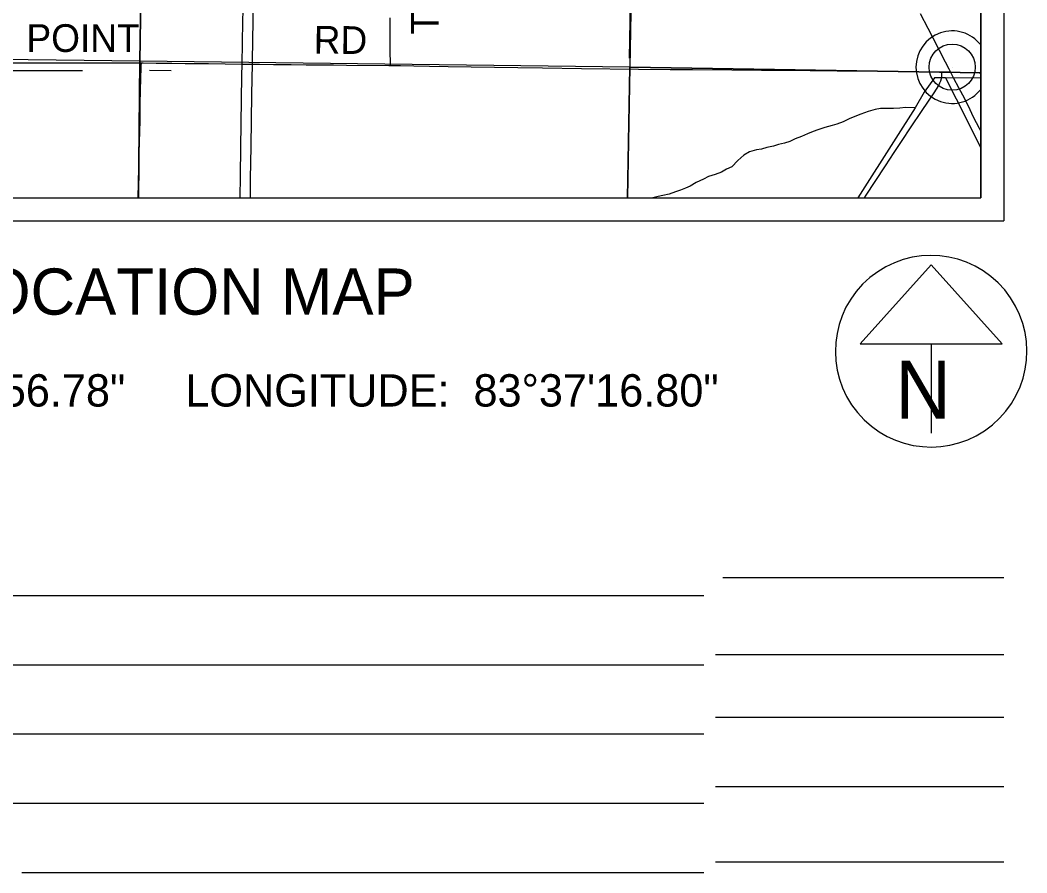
# Model space of a CAD drawing. Extents: x -5.6 to 34, y 0 to 22.
# Drawn here: x 4.739 to 9.099, y 11.177 to 14.869 of the extents above; entities that cross this region are included whole.
import ezdxf

# ---------------------------------------------------------------- set-up
doc = ezdxf.new("R2010")
doc.units = 0
for name, color, linetype in [('GM_X_Interstate_Route', 7, 'Continuous'), ('GM_X_Minor_River', 7, 'Continuous'), ('GM_X_Section', 7, 'Continuous'), ('GM_X_State_Route', 7, 'Continuous'), ('GM_X_Township', 7, 'Continuous'), ('GM_X_Township_Road', 7, 'Continuous'), ('GM_X_Township_Road_Text', 7, 'Continuous'), ('GM_X_Unincorporated', 7, 'Continuous'), ('GM_X_Unincorporated_Location', 7, 'Continuous'), ('SH_Data', 7, 'Continuous'), ('SH_Text', 7, 'Continuous')]:
    doc.layers.add(name, color=color, linetype=linetype)

msp = doc.modelspace()

# ---------------------------------------------------------------- linework, layer by layer
at = {"layer": 'GM_X_Interstate_Route'}
for points in [[(5.7358, 14.1), (5.7369, 14.1817), (5.7387, 14.3222), (5.7425, 14.5493), (5.7447, 14.6786), (5.745, 14.6938), (5.7503, 15.0391)], [(5.6912, 14.1), (5.6926, 14.1951), (5.6944, 14.3172), (5.6993, 14.6284), (5.7002, 14.6792), (5.7034, 14.8634), (5.704, 14.912)]]:
    msp.add_lwpolyline(points, dxfattribs=at)
at = {"layer": 'GM_X_Minor_River'}
for points in [[(7.3779, 14.7044), (7.3837, 15.0298), (7.3962, 15.4993), (7.4047, 15.9625), (7.4129, 16.2894), (7.4222, 16.7566)], [(3.6761, 14.6605), (3.815, 14.6604), (3.9826, 14.6579), (4.2141, 14.6562), (4.4447, 14.6522), (4.701, 14.6508), (5.0092, 14.6513)], [(5.299, 14.6523), (5.3932, 14.6508)], [(8.9, 14.6183), (8.7475, 14.6191), (8.6988, 14.6197), (8.6541, 14.5578), (8.615, 14.4901), (8.5311, 14.3581), (8.3669, 14.1)], [(8.7475, 14.6191), (8.8393, 14.4376), (8.9, 14.3153)], [(8.615, 14.4901), (8.5743, 14.4907), (8.5495, 14.4878), (8.5216, 14.4865), (8.4928, 14.4869), (8.4657, 14.4864), (8.4417, 14.4827), (8.4121, 14.4735), (8.38, 14.4626), (8.3544, 14.4517), (8.3303, 14.4416), (8.303, 14.4283), (8.2765, 14.419), (8.2565, 14.4129), (8.2237, 14.4045), (8.1933, 14.3944), (8.1732, 14.3875), (8.1491, 14.3766), (8.1227, 14.3657), (8.0954, 14.3548), (8.0729, 14.3438), (8.0497, 14.3369), (8.0241, 14.3308), (8.0024, 14.3239), (7.9736, 14.3178), (7.9496, 14.3109), (7.928, 14.3072), (7.8976, 14.2995), (7.8727, 14.2838), (7.8477, 14.2617), (7.8218, 14.234), (7.7985, 14.2238), (7.776, 14.2113), (7.7495, 14.2012), (7.7199, 14.192), (7.6982, 14.181), (7.6669, 14.1662), (7.6412, 14.1505), (7.6211, 14.1411), (7.5995, 14.1334), (7.577, 14.1264), (7.5506, 14.1163), (7.5226, 14.1103), (7.5018, 14.1049), (7.479, 14.1)]]:
    msp.add_lwpolyline(points, dxfattribs=at)
at = {"layer": 'GM_X_Section'}
for points in [[(3.1401, 16.8587), (5.2895, 16.8144), (5.2575, 14.6921), (3.0791, 14.7168)], [(5.2895, 16.8144), (7.4183, 16.7871), (7.3798, 14.6657), (5.2575, 14.6921)], [(8.9, 14.6404), (8.9, 16.7658), (7.4183, 16.7871), (7.3798, 14.6657)], [(3.0658, 14.1), (5.2509, 14.1), (5.2575, 14.6921), (3.0791, 14.7168)], [(5.2509, 14.1), (7.3694, 14.1), (7.3798, 14.6657), (5.2575, 14.6921)], [(7.3694, 14.1), (8.9, 14.1), (8.9, 14.6404), (7.3798, 14.6657)]]:
    msp.add_lwpolyline(points, close=True, dxfattribs=at)
at = {"layer": 'GM_X_State_Route'}
msp.add_lwpolyline([(8.9, 14.3878), (8.8937, 14.4001), (8.8685, 14.4496), (8.8531, 14.4812), (8.8331, 14.5221), (8.8225, 14.5437), (8.805, 14.576), (8.7836, 14.6167), (8.7688, 14.6447), (8.7622, 14.6573), (8.7464, 14.6876), (8.7205, 14.7377), (8.693, 14.7915), (8.6718, 14.8323), (8.6388, 14.8965)], dxfattribs=at)
at = {"layer": 'GM_X_Township'}
msp.add_lwpolyline([(3.0636, 14.1), (8.9, 14.1), (8.9, 20.9), (2.1, 20.9), (2.1, 16.9108), (2.7242, 16.8707), (3.1388, 16.8616), (3.0745, 14.7121)], close=True, dxfattribs=at)
at = {"layer": 'GM_X_Township_Road'}
for points in [[(6.3425, 14.6731), (6.3422, 14.6863), (6.3415, 14.7298), (6.3416, 14.7561), (6.3416, 14.8073), (6.3418, 14.8796)], [(4.4977, 14.6847), (4.6113, 14.6845), (4.7391, 14.684), (4.843, 14.684), (5.0184, 14.6841), (5.1773, 14.6846), (5.2635, 14.6842)], [(5.2502, 14.1), (5.2541, 14.2953), (5.2579, 14.4332), (5.2591, 14.4989), (5.26, 14.5711), (5.2608, 14.6106), (5.263, 14.6696), (5.2635, 14.6842)], [(5.2635, 14.6842), (5.2718, 14.6842), (5.3271, 14.6834), (5.3953, 14.6824), (5.4531, 14.6818), (5.5541, 14.6812), (5.6263, 14.6801), (5.7002, 14.6792), (5.7104, 14.679), (5.7447, 14.6786), (5.7747, 14.6783), (5.8364, 14.6777), (5.9126, 14.677), (5.9782, 14.676), (6.0333, 14.6756), (6.0954, 14.675), (6.1528, 14.6746), (6.3349, 14.6733), (6.3425, 14.6731)], [(6.3425, 14.6731), (6.386, 14.6723), (6.4443, 14.6712), (6.5113, 14.6702), (6.5921, 14.669), (6.6925, 14.6674), (6.8947, 14.6641), (7.0011, 14.6626), (7.1705, 14.6598), (7.4174, 14.6567), (7.5539, 14.6557), (7.6511, 14.6552), (7.8218, 14.654), (7.9492, 14.6528), (8.0425, 14.652), (8.2775, 14.6497), (8.4692, 14.6486), (8.5875, 14.6473), (8.724, 14.6455), (8.7315, 14.6454)], [(8.396, 14.1), (8.4038, 14.1119), (8.442, 14.17), (8.4863, 14.2383), (8.5247, 14.2963), (8.5539, 14.34), (8.6007, 14.4114), (8.6407, 14.4699), (8.6758, 14.5223), (8.6977, 14.555), (8.7174, 14.5863), (8.7228, 14.597), (8.7268, 14.6068), (8.7295, 14.6159), (8.7309, 14.6239), (8.731, 14.6294), (8.7315, 14.6454)], [(8.7315, 14.6454), (8.7688, 14.6447)], [(8.7688, 14.6447), (8.7897, 14.6443), (8.8514, 14.6422), (8.8934, 14.6406), (8.9, 14.6404)]]:
    msp.add_lwpolyline(points, dxfattribs=at)
at = {"layer": 'GM_X_Unincorporated'}
msp.add_line((8.9, 14.5693), (8.9, 14.7619), dxfattribs=at)
msp.add_circle((8.7758, 14.6656), 0.0996, dxfattribs=at)
msp.add_arc((8.7758, 14.6656), 0.1571, 37.7831, 322.2169, dxfattribs=at)
at = {"layer": 'GM_X_Unincorporated_Location'}
msp.add_line((8.7758, 14.6656), (8.7758, 14.6656), dxfattribs=at)
at = {"layer": 'SH_Data'}
for p, q in [((9, 21), (9, 14)), ((8.9, 20.9), (8.9, 14.1)), ((2.1, 14.1), (8.9, 14.1)), ((2, 14), (9, 14)), ((8.6845, 13.8091), (8.3769, 13.4678)), ((8.9921, 13.4678), (8.6845, 13.8091)), ((8.3769, 13.4678), (8.9921, 13.4678)), ((8.6845, 13.4678), (8.6845, 13.0811)), ((8.6845, 13.4353), (8.6845, 13.4353)), ((8.6845, 13.4353), (8.6845, 13.4353)), ((7.7827, 12.4553), (9, 12.4553)), ((7.7, 12.3767), (4.4937, 12.3767)), ((9, 12.1207), (7.75, 12.1207)), ((7.7, 12.0767), (3.9895, 12.0767)), ((9, 11.8491), (7.75, 11.8491)), ((7.7, 11.7767), (3.6192, 11.7767)), ((9, 11.5491), (7.75, 11.5491)), ((7.7, 11.4767), (3.3288, 11.4767)), ((9, 11.2223), (7.75, 11.2223)), ((7.7, 11.1767), (4.7452, 11.1767))]:
    msp.add_line(p, q, dxfattribs=at)
msp.add_arc((8.6845, 13.4353), 0.4148, 129.7798, 129.7633, dxfattribs=at)

# ---------------------------------------------------------------- texts
at = {"layer": 'GM_X_Township_Road_Text'}
for s, rotation, p in [('T-299', 90, (6.5511, 14.8075)), ('POINT', 0, (4.7659, 14.7315)), ('RD', 359.5086, (6.0098, 14.7244))]:
    msp.add_text(s, height=0.12, rotation=rotation, dxfattribs=at).set_placement(p)
at = {"layer": 'SH_Data'}
msp.add_text('N', height=0.25, dxfattribs=at).set_placement((8.5292, 13.144))
at = {"layer": 'SH_Text'}
for s, height, p in [('LOCATION MAP', 0.2, (4.4269, 13.5938)), ('LATITUDE:  41°31\'56.78"     LONGITUDE:  83°37\'16.80"', 0.14, (3.071, 13.1959))]:
    msp.add_text(s, height=height, dxfattribs=at).set_placement(p)

doc.saveas('drawing.dxf')
